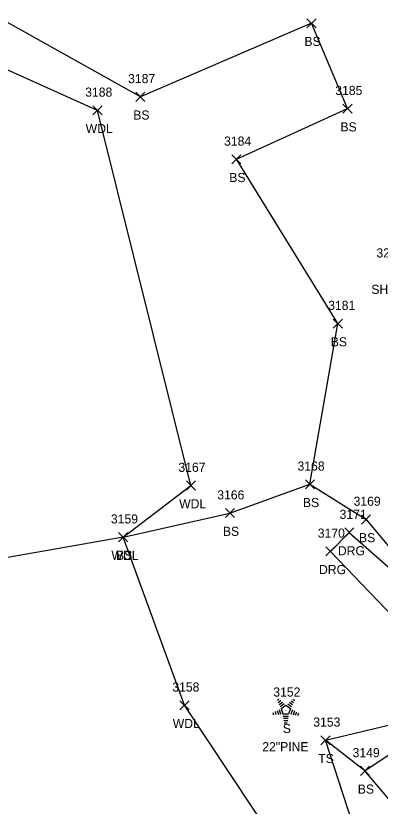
# Model space of a CAD drawing. Extents: x 1601151 to 1602912, y 499508 to 501770.
# Drawn here: x 1601482.2 to 1601562.2, y 500341.3 to 500514.8 of the extents above; entities that cross this region are included whole.
import ezdxf

# ---------------------------------------------------------------- set-up
doc = ezdxf.new("R2010")
doc.units = 0
for name, color, linetype in [('L_A', 7, 'Continuous'), ('L_C', 7, 'Continuous'), ('L_I', 7, 'Continuous'), ('L_TIC', 7, 'Continuous'), ('LAWA', 7, 'Continuous'), ('LELB', 7, 'Continuous'), ('LTC', 7, 'Continuous'), ('R_A', 7, 'Continuous'), ('R_I', 7, 'Continuous'), ('R_TIC', 7, 'Continuous'), ('RDG', 7, 'Continuous')]:
    doc.layers.add(name, color=color, linetype=linetype)

msp = doc.modelspace()

# ---------------------------------------------------------------- linework, layer by layer
at = {"layer": 'L_TIC'}
for points in [[(1601546.11, 500512.14), (1601548.11, 500514.14)], [(1601548.11, 500512.14), (1601546.11, 500514.14)], [(1601508.53, 500495.99), (1601510.53, 500497.99)], [(1601510.53, 500495.99), (1601508.53, 500497.99)], [(1601499.1, 500493.02), (1601501.1, 500495.02)], [(1601501.1, 500493.02), (1601499.1, 500495.02)], [(1601554.01, 500493.39), (1601556.01, 500495.39)], [(1601556.01, 500493.39), (1601554.01, 500495.39)], [(1601529.6, 500482.27), (1601531.6, 500484.27)], [(1601531.6, 500482.27), (1601529.6, 500484.27)], [(1601551.89, 500446.21), (1601553.89, 500448.21)], [(1601553.89, 500446.21), (1601551.89, 500448.21)], [(1601519.62, 500410.67), (1601521.62, 500412.67)], [(1601521.62, 500410.67), (1601519.62, 500412.67)], [(1601545.77, 500410.94), (1601547.77, 500412.94)], [(1601547.77, 500410.94), (1601545.77, 500412.94)], [(1601545.77, 500410.94), (1601547.77, 500412.94)], [(1601547.77, 500410.94), (1601545.77, 500412.94)], [(1601528.2, 500404.62), (1601530.2, 500406.62)], [(1601530.2, 500404.62), (1601528.2, 500406.62)], [(1601558.09, 500403.22), (1601560.09, 500405.22)], [(1601560.09, 500403.22), (1601558.09, 500405.22)], [(1601504.75, 500399.34), (1601506.75, 500401.34)], [(1601506.75, 500399.34), (1601504.75, 500401.34)], [(1601504.75, 500399.34), (1601506.75, 500401.34)], [(1601506.75, 500399.34), (1601504.75, 500401.34)], [(1601504.75, 500399.34), (1601506.75, 500401.34)], [(1601506.75, 500399.34), (1601504.75, 500401.34)], [(1601518.22, 500362.44), (1601520.22, 500364.44)], [(1601520.22, 500362.44), (1601518.22, 500364.44)], [(1601549.18, 500354.75), (1601551.18, 500356.75)], [(1601551.18, 500354.75), (1601549.18, 500356.75)], [(1601557.83, 500348.04), (1601559.83, 500350.04)], [(1601559.83, 500348.04), (1601557.83, 500350.04)]]:
    msp.add_lwpolyline(points, dxfattribs=at)
at = {"layer": 'LAWA'}
msp.add_lwpolyline([(1601544.34, 500325.67), (1601519.22, 500363.44), (1601505.75, 500400.34), (1601520.62, 500411.67), (1601500.1, 500494.02), (1601464.79, 500509.89), (1601431.61, 500509.7), (1601398.17, 500505.26), (1601396.59, 500512.31), (1601395.61, 500523.84), (1601392.91, 500532.17), (1601391.39, 500554.19), (1601400.22, 500561.71), (1601429.3, 500567.09), (1601477.41, 500577.92), (1601523.77, 500579.55), (1601560.2, 500571.77), (1601556.37, 500545), (1601575.25, 500522.25), (1601572.33, 500557.32), (1601570.48, 500566.05)], dxfattribs=at)
at = {"layer": 'LELB'}
for points in [[(1601505.75, 500400.34), (1601529.2, 500405.62), (1601546.77, 500411.94), (1601552.89, 500447.21), (1601530.6, 500483.27), (1601555.01, 500494.39), (1601547.11, 500513.14), (1601509.53, 500496.99), (1601471.63, 500518.1), (1601429.12, 500515.55), (1601396.59, 500512.31), (1601368.25, 500492.88)], [(1601546.77, 500411.94), (1601559.09, 500404.22), (1601578.47, 500381.05), (1601598.94, 500368.33)], [(1601505.75, 500400.34), (1601469.15, 500393.86)], [(1601614.36, 500342.29), (1601582.87, 500335.78), (1601557.91, 500331.9), (1601550.18, 500355.75), (1601579.12, 500362.69)], [(1601614.36, 500342.29), (1601580.01, 500339.37), (1601567.07, 500339.35), (1601558.83, 500349.04), (1601579.12, 500362.69)], [(1601558.83, 500349.04), (1601550.18, 500355.75)]]:
    msp.add_lwpolyline(points, dxfattribs=at)
at = {"layer": 'LTC'}
for p, q in [((1601539.6, 500364.55), (1601539.96, 500364.81)), ((1601543, 500364.79), (1601543.42, 500364.49)), ((1601539.81, 500364.08), (1601540.34, 500364.47)), ((1601540.02, 500363.62), (1601540.73, 500364.13)), ((1601540.23, 500363.15), (1601541.11, 500363.79)), ((1601540.46, 500362.7), (1601541.47, 500363.43)), ((1601541.47, 500363.43), (1601542.46, 500362.71)), ((1601541.89, 500363.75), (1601542.7, 500363.16)), ((1601542.26, 500364.09), (1601542.94, 500363.6)), ((1601542.63, 500364.44), (1601543.18, 500364.04)), ((1601538.63, 500361.83), (1601538.79, 500361.36)), ((1601539.09, 500362.05), (1601539.3, 500361.39)), ((1601539.55, 500362.26), (1601539.82, 500361.43)), ((1601540, 500362.48), (1601540.33, 500361.46)), ((1601540.46, 500362.7), (1601540.84, 500361.5)), ((1601542.07, 500361.5), (1601540.84, 500361.5)), ((1601542.46, 500362.71), (1601542.07, 500361.5)), ((1601542.9, 500362.44), (1601542.56, 500361.4)), ((1601543.35, 500362.19), (1601543.06, 500361.3)), ((1601543.79, 500361.94), (1601543.55, 500361.21)), ((1601544.24, 500361.69), (1601544.05, 500361.11)), ((1601542.03, 500361), (1601540.89, 500361)), ((1601541.95, 500360.5), (1601540.96, 500360.5)), ((1601541.87, 500360), (1601541.04, 500360)), ((1601541.78, 500359.5), (1601541.11, 500359.5))]:
    msp.add_line(p, q, dxfattribs=at)
at = {"layer": 'R_TIC'}
for points in [[(1601554.4, 500400.35), (1601556.4, 500402.35)], [(1601556.4, 500400.35), (1601554.4, 500402.35)], [(1601550.26, 500396.22), (1601552.26, 500398.22)], [(1601552.26, 500396.22), (1601550.26, 500398.22)]]:
    msp.add_lwpolyline(points, dxfattribs=at)
at = {"layer": 'RDG'}
msp.add_lwpolyline([(1601598.43, 500347.96), (1601580.84, 500366.39), (1601551.26, 500397.22), (1601555.4, 500401.35), (1601578.47, 500381.05), (1601607.6, 500359.44)], dxfattribs=at)

# ---------------------------------------------------------------- texts
at = {"layer": 'L_A'}
for s, p in [('BS', (1601545.55, 500508.14)), ('BS', (1601507.97, 500491.99)), ('BS', (1601553.45, 500489.39)), ('WDL', (1601497.52, 500489.02)), ('BS', (1601529.04, 500478.27)), ('SHRUB', (1601560.24, 500453.72)), ('BS', (1601551.33, 500442.21)), ('WDL', (1601518.04, 500406.67)), ('BS', (1601545.21, 500406.94)), ('BS', (1601545.21, 500406.94)), ('BS', (1601527.64, 500400.62)), ('BS', (1601557.53, 500399.22)), ('WDL', (1601503.17, 500395.34)), ('BS', (1601504.19, 500395.34)), ('BS', (1601504.19, 500395.34)), ('WDL', (1601516.64, 500358.44)), ('S', (1601540.79, 500357.34)), ('TS', (1601548.59, 500350.75)), ('BS', (1601557.27, 500344.04))]:
    msp.add_text(s, height=2, dxfattribs=at).set_placement(p)
at = {"layer": 'L_C'}
msp.add_text('22"PINE', height=2, dxfattribs=at).set_placement((1601536.29, 500353.34))
at = {"layer": 'L_I'}
for s, p in [('3187', (1601506.83, 500499.99)), ('3188', (1601497.41, 500497.02)), ('3185', (1601552.32, 500497.39)), ('3184', (1601527.91, 500486.27)), ('3222', (1601561.35, 500461.72)), ('3181', (1601550.76, 500450.21)), ('3168', (1601544.03, 500414.94)), ('3168', (1601544.03, 500414.94)), ('3167', (1601517.88, 500414.67)), ('3166', (1601526.41, 500408.62)), ('3169', (1601556.34, 500407.22)), ('3159', (1601503.05, 500403.34)), ('3159', (1601503.05, 500403.34)), ('3159', (1601503.05, 500403.34)), ('3158', (1601516.53, 500366.44)), ('3152', (1601538.71, 500365.34)), ('3153', (1601547.49, 500358.75)), ('3149', (1601556.13, 500352.04))]:
    msp.add_text(s, height=2, dxfattribs=at).set_placement(p)
at = {"layer": 'LTC'}
msp.add_text('.', height=1.04, rotation=270, dxfattribs=at).set_placement((1601541.35, 500362.45))
at = {"layer": 'R_A'}
for p in [(1601552.89, 500396.35), (1601548.75, 500392.22)]:
    msp.add_text('DRG', height=2, dxfattribs=at).set_placement(p)
at = {"layer": 'R_I'}
for s, p in [('3171', (1601553.27, 500404.35)), ('3170', (1601548.48, 500400.22))]:
    msp.add_text(s, height=2, dxfattribs=at).set_placement(p)

doc.saveas('drawing.dxf')
